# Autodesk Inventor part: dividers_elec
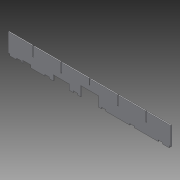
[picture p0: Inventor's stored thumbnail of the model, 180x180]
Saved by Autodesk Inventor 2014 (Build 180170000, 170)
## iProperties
Created: 2014-05
Part Number: dividers_elec
Material: ABS Plastic
Document SubType Name: Modeling
Designer: t_emanb
Density: 1 g/cm^3
Appearance: Smooth - White
Author: t_emanb
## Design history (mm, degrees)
sketch "Sketch1"
  geometry: L1 (0, 0)-(584.2, 0); L2 (584.2, 0)-(584.2, 72.39); L3 (584.2, 72.39)-(0, 72.39); L4 (0, 72.39)-(0, 0)
  constraints: 8 end point, 2 parallel, 1 horizontal, 1 perpendicular
  dimensions: "d0" = 584.2 distance of L2.end L3.end; "d1" = 72.39 distance of L3.end L1.start
extrude "Extrusion1" new body sketch "Sketch1" distance "d2" = 3.048; taper "d3" = 0 deg
sketch "Sketch2" dims "d9" = 25.4, "d20" = 25.4, "d32" = 25.4
  geometry: L1 (88.9, 72.39)-(88.9, 0); L2 (190.5, 72.39)-(190.5, 0); L3 (292.1, 72.39)-(292.1, 0); L4 (393.7, 72.39)-(393.7, 0); L5 (495.3, 72.39)-(495.3, 0); L6 (139.7, 72.39)-(139.7, 0); L7 (38.1, 0)-(38.1, 72.39); L8 (241.3, 0)-(241.3, 72.39); L9 (342.9, 72.39)-(342.9, 0); L10 (444.5, 0)-(444.5, 72.39); L11 (546.1, 72.39)-(546.1, 0); L12 (131.762, 0)-(147.638, 0); L13 (147.638, 0)-(147.638, 5.08); L14 (147.638, 5.08)-(131.763, 5.08); L15 (131.763, 5.08)-(131.762, 0); L16 (249.238, 5.08)-(233.363, 5.08); L17 (233.363, 5.08)-(233.363, 0); L18 (233.363, 0)-(249.238, 0); L19 (249.238, 0)-(249.238, 5.08); L20 (350.838, 5.08)-(334.963, 5.08); L21 (334.963, 5.08)-(334.963, 0); L22 (334.963, 0)-(350.838, 0); L23 (350.838, 0)-(350.838, 5.08); L24 (452.438, 5.08)-(436.562, 5.08); L25 (436.562, 5.08)-(436.562, 0); L26 (436.562, 0)-(452.438, 0); L27 (452.438, 0)-(452.438, 5.08); L28 (554.038, 5.08)-(538.162, 5.08); L29 (538.162, 5.08)-(538.162, 0); L30 (538.162, 0)-(554.038, 0); L31 (554.038, 0)-(554.038, 5.08); L32 (30.163, 0)-(46.037, 0); L33 (46.037, 0)-(46.037, 5.08); L34 (46.037, 5.08)-(30.163, 5.08); L35 (30.163, 5.08)-(30.163, 0); L36 (87.376, 72.39)-(90.424, 72.39); L37 (90.424, 72.39)-(90.424, 38.1); L38 (90.424, 38.1)-(87.376, 38.1); L39 (87.376, 38.1)-(87.376, 72.39); L40 (188.976, 38.1)-(188.976, 72.39); L41 (188.976, 72.39)-(192.024, 72.39); L42 (192.024, 72.39)-(192.024, 38.1); L43 (192.024, 38.1)-(188.976, 38.1); L44 (290.576, 38.1)-(290.576, 72.39); L45 (290.576, 72.39)-(293.624, 72.39); L46 (293.624, 72.39)-(293.624, 38.1); L47 (293.624, 38.1)-(290.576, 38.1); L48 (392.176, 38.1)-(392.176, 72.39); L49 (392.176, 72.39)-(395.224, 72.39); L50 (395.224, 72.39)-(395.224, 38.1); L51 (395.224, 38.1)-(392.176, 38.1); L52 (493.776, 38.1)-(493.776, 72.39); L53 (493.776, 72.39)-(496.824, 72.39); L54 (496.824, 72.39)-(496.824, 38.1); L55 (496.824, 38.1)-(493.776, 38.1); L56 (290.576, 52.07)-(293.624, 52.07); 4 further points
  constraints: 112 end point, 40 horizontal alignment, 26 parallel, 16 collinear, 7 vertical, 4 perpendicular, 3 horizontal, 2 point on line, 26 other
  dimensions: "d6" = 101.6 distance of L1.start L2.start; "d11" = 50.8 distance between parallel lines of L11 L5; "d12" = 50.8 distance between parallel lines of L1 L7; "d13" = 15.875 distance of L13.end L14.end; "d14" = 5.08 distance of L12.end L13.end; "d17" = 101.6 distance of L13.end L16.start; "d22" = 5.08 distance of L32.end L33.end; "d24" = 3.048 distance of L37.end L38.end; "d25" = 38.1 distance of the line from the sketch origin of L38; "d26" = 1.524 distance between parallel lines of L37 L1 (= 0.5 x d24); "d29" = 101.6 distance of L38.end L40.start; "d42" = 15.875 distance between parallel lines of L35 L33 (= d13); "d52" = 20.32 distance between parallel lines of L45 L56
extrude "Extrusion2" cut sketch "Sketch2" stored distance "d34" = 3.175; taper "d35" = 0 deg
sketch "Sketch3"
  geometry: L1 (554.038, 0)-(584.2, 0) reference; L2 (584.2, 0)-(584.2, 72.39) reference; L3 (0, 72.39)-(0, 0) reference; L4 (0, 0)-(30.163, 0) reference; L5 (538.162, 5.08)-(554.038, 5.08) reference; L6 (0, 6.35)-(6.35, 6.35); L7 (584.2, 6.35)-(577.85, 6.35); L8 (577.85, 6.35)-(577.85, 0); L9 (6.35, 6.35)-(6.35, 0)
  constraints: 8 end point, 4 point on line, 3 perpendicular, 1 parallel
  dimensions: "d36" = 6.35 distance of L7.start L7.end; "d37" = 6.35 distance of L6.start L6.end (= d36); "d38" = 6.35 distance of L7.end L8.end; "d39" = 6.35 distance of L6.end L9.end (= d38)
extrude "Extrusion3" cut sketch "Sketch3" stored distance "d40" = 25.4; taper "d41" = 0 deg
sketch "Sketch4"
  geometry: L1 (192.024, 72.39)-(192.024, 38.1) reference; L2 (192.024, 38.1)-(188.976, 38.1) reference; L3 (147.638, 0)-(233.363, 0) reference; L4 (249.238, 0)-(334.963, 0) reference; L5 (161.925, 0)-(219.075, 0); L6 (219.075, 0)-(219.075, 19.05); L7 (219.075, 19.05)-(161.925, 19.05); L8 (161.925, 19.05)-(161.925, 0); L9 (260.35, 0)-(323.85, 0); L10 (323.85, 0)-(323.85, 34.925); L11 (323.85, 34.925)-(260.35, 34.925); L12 (260.35, 34.925)-(260.35, 0); L13 (190.5, 38.1)-(190.5, 71.438); L14 (46.037, 5.08)-(46.037, 0) reference; L15 (46.037, 0)-(131.762, 0) reference; L16 (554.038, 0)-(577.85, 0) reference; L17 (52.388, 0)-(52.388, 9.525); L18 (52.388, 9.525)-(80.962, 9.525); L19 (80.962, 9.525)-(80.962, 0); L20 (293.624, 52.07)-(290.576, 52.07) reference; L21 (292.1, 52.07)-(292.1, 0); 1 further point
  constraints: 26 end point, 5 parallel, 5 perpendicular, 4 point on line, 3 midpoint, 2 horizontal, 2 other
  dimensions: "d43" = 63.5 distance of L10.end L11.end; "d44" = 57.15 distance of L6.end L7.end; "d45" = 19.05 distance of L5.end L6.end; "d46" = 34.925 distance of L9.end L10.end; "d49" = 28.575 distance of L17.end L18.end; "d50" = 9.525 distance of L18.end L19.end; "d51" = 6.35 distance between parallel lines of L14 L17
extrude "Extrusion4" cut sketch "Sketch4" stored distance "d47" = 25.4; taper "d48" = 0 deg
body "Solid1"
